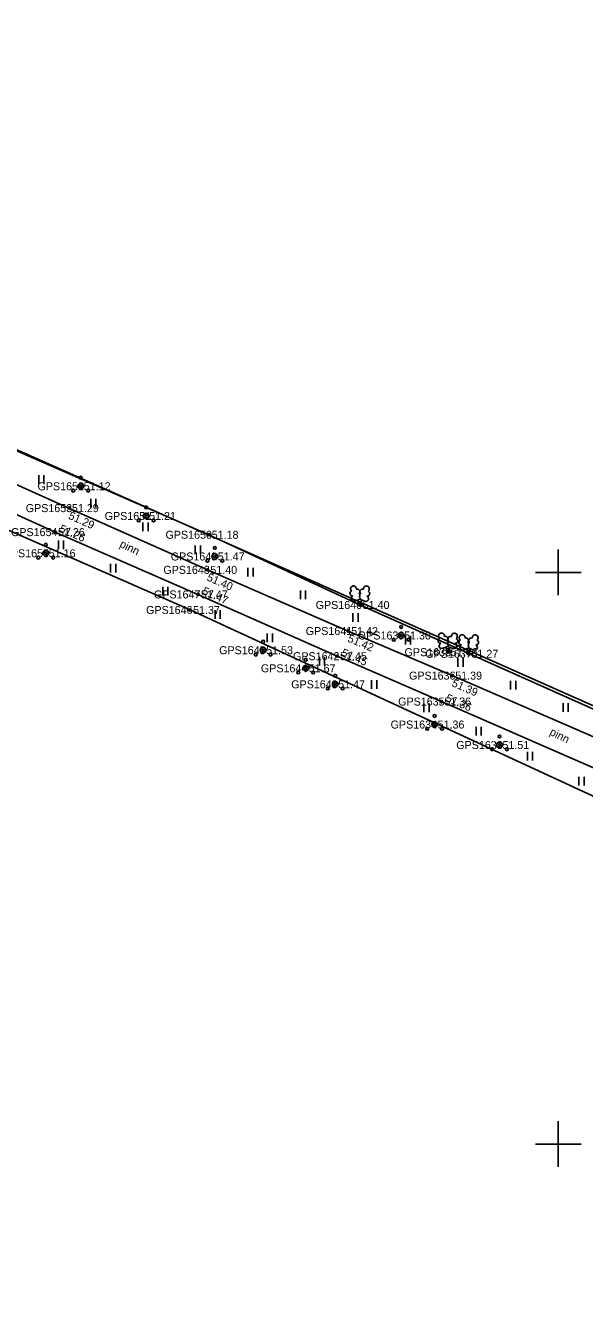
# Model space of a CAD drawing. Extents: x 551623 to 559850, y 6561220 to 6567135.
# Drawn here: x 556303.4 to 556352.3, y 6565186.2 to 6565297.8 of the extents above; entities that cross this region are included whole.
import ezdxf

# ---------------------------------------------------------------- set-up
doc = ezdxf.new("R2010")
doc.units = 0
for name, color, linetype in [('HALJASTUS', 7, 'Continuous'), ('KORGUS-EH2000', 7, 'Continuous'), ('MOOTKORG-EH2000', 7, 'Continuous'), ('MOOTMPUNKT', 7, 'Continuous'), ('MOOTNR', 7, 'Continuous'), ('MOOTPIIR', 7, 'Continuous'), ('PIIR', 7, 'Continuous'), ('PUU', 7, 'Continuous'), ('TEE', 7, 'Continuous'), ('VORK', 7, 'Continuous')]:
    doc.layers.add(name, color=color, linetype=linetype)

msp = doc.modelspace()

# ---------------------------------------------------------------- linework, layer by layer
at = {"layer": 'HALJASTUS'}
for p, q in [((556304.57, 6565258.49), (556304.57, 6565257.73)), ((556305.03, 6565258.49), (556305.03, 6565257.73)), ((556309.12, 6565256.42), (556309.12, 6565255.66)), ((556309.58, 6565256.42), (556309.58, 6565255.66)), ((556313.67, 6565254.35), (556313.67, 6565253.59)), ((556314.13, 6565254.35), (556314.13, 6565253.59)), ((556306.29, 6565252.8), (556306.29, 6565252.04)), ((556306.74, 6565252.8), (556306.74, 6565252.04)), ((556318.26, 6565252.36), (556318.26, 6565251.6)), ((556318.72, 6565252.36), (556318.72, 6565251.6)), ((556310.85, 6565250.76), (556310.85, 6565250)), ((556311.31, 6565250.76), (556311.31, 6565250)), ((556322.85, 6565250.39), (556322.85, 6565249.63)), ((556323.31, 6565250.39), (556323.31, 6565249.63)), ((556315.42, 6565248.73), (556315.42, 6565247.97)), ((556315.87, 6565248.73), (556315.87, 6565247.97)), ((556327.45, 6565248.41), (556327.45, 6565247.65)), ((556327.9, 6565248.41), (556327.9, 6565247.65)), ((556319.99, 6565246.69), (556319.99, 6565245.93)), ((556320.44, 6565246.69), (556320.44, 6565245.93)), ((556332.04, 6565246.44), (556332.04, 6565245.68)), ((556332.5, 6565246.44), (556332.5, 6565245.68)), ((556324.55, 6565244.65), (556324.55, 6565243.89)), ((556325.01, 6565244.65), (556325.01, 6565243.89)), ((556336.64, 6565244.46), (556336.64, 6565243.7)), ((556337.09, 6565244.46), (556337.09, 6565243.7)), ((556329.12, 6565242.62), (556329.12, 6565241.86)), ((556329.57, 6565242.62), (556329.57, 6565241.86)), ((556341.23, 6565242.49), (556341.23, 6565241.73)), ((556341.68, 6565242.49), (556341.68, 6565241.73)), ((556333.68, 6565240.58), (556333.68, 6565239.82)), ((556334.14, 6565240.58), (556334.14, 6565239.82)), ((556345.82, 6565240.52), (556345.82, 6565239.76)), ((556346.28, 6565240.52), (556346.28, 6565239.76)), ((556338.25, 6565238.54), (556338.25, 6565237.78)), ((556338.71, 6565238.54), (556338.71, 6565237.78)), ((556350.42, 6565238.55), (556350.42, 6565237.79)), ((556350.87, 6565238.55), (556350.87, 6565237.79)), ((556342.81, 6565236.48), (556342.81, 6565235.72)), ((556343.26, 6565236.48), (556343.26, 6565235.72)), ((556347.31, 6565234.3), (556347.31, 6565233.54)), ((556347.76, 6565234.3), (556347.76, 6565233.54)), ((556351.81, 6565232.13), (556351.81, 6565231.36)), ((556352.26, 6565232.13), (556352.26, 6565231.36))]:
    msp.add_line(p, q, dxfattribs=at)
at = {"layer": 'KORGUS-EH2000'}
for centre in [(556308.25, 6565257.53), (556307.22, 6565255.62), (556306, 6565253.52), (556319.44, 6565253.29), (556305.19, 6565251.67), (556319.32, 6565250.22), (556318.5, 6565248.07), (556332.64, 6565247.15), (556317.81, 6565246.71), (556331.63, 6565244.87), (556330.66, 6565242.67), (556342.15, 6565242.88), (556330.5, 6565240.21), (556340.73, 6565240.97), (556339.78, 6565238.7), (556339.19, 6565236.69)]:
    msp.add_circle(centre, 0.1, dxfattribs=at)
at = {"layer": 'MOOTMPUNKT'}
for centre in [(556308.25, 6565257.53), (556307.22, 6565255.62), (556313.97, 6565254.93), (556306, 6565253.52), (556319.44, 6565253.29), (556305.19, 6565251.67), (556319.97, 6565251.39), (556319.32, 6565250.22), (556318.5, 6565248.07), (556332.64, 6565247.15), (556317.81, 6565246.71), (556331.63, 6565244.87), (556336.26, 6565244.48), (556324.2, 6565243.19), (556330.66, 6565242.67), (556340.34, 6565243.02), (556342.15, 6565242.88), (556327.92, 6565241.61), (556330.5, 6565240.21), (556340.73, 6565240.97), (556339.78, 6565238.7), (556339.19, 6565236.69), (556344.86, 6565234.9)]:
    msp.add_circle(centre, 0.1, dxfattribs=at)
at = {"layer": 'MOOTPIIR'}
for points in [[(556444.3, 6565198.68), (556419.03, 6565208.86), (556407.25, 6565214.28), (556381.48, 6565225.36), (556332.64, 6565247.15), (556319.44, 6565253.29), (556278.3, 6565271.26)], [(556293.31, 6565257.46), (556317.81, 6565246.71), (556360.31, 6565227.07), (556390.3, 6565214.09), (556436.48, 6565194.19), (556449.65, 6565188.22)]]:
    msp.add_lwpolyline(points, dxfattribs=at)
at = {"layer": 'PIIR'}
for points in [[(556217.39, 6565298.59), (556213.87, 6565303.19), (556229.81, 6565311.25), (556335.44, 6565331.24), (556350.73, 6565342.07), (556507.54, 6565334), (556519.21, 6565368.05), (556548.5, 6565368.1), (556612.15, 6565380.04), (556615.14, 6565380.2), (556613.56, 6565366.23), (556611.32, 6565356.67), (556591.74, 6565273.2), (556570.09, 6565180.67), (556561.87, 6565145.74), (556557.67, 6565147.61), (556393.49, 6565220.36)], [(556206.35, 6565280.04), (556217.39, 6565298.59), (556393.49, 6565220.36), (556274.8, 6564990.28), (556228.34, 6565008.72), (556105.05, 6565057.69), (556140.52, 6565135.89), (556229.38, 6565104.35), (556274.08, 6565194.99), (556184.08, 6565232.1), (556196.52, 6565258.88), (556203.12, 6565272.11)]]:
    msp.add_lwpolyline(points, close=True, dxfattribs=at)
at = {"layer": 'PUU'}
for p, q in [((556332.2, 6565247.48), (556332.65, 6565247.66)), ((556332.64, 6565247.15), (556332.47, 6565247.59)), ((556332.64, 6565247.15), (556332.82, 6565247.59)), ((556333.02, 6565247.15), (556332.64, 6565247.15)), ((556332.65, 6565247.66), (556333.09, 6565247.48)), ((556339.9, 6565243.36), (556340.35, 6565243.53)), ((556340.34, 6565243.02), (556340.17, 6565243.46)), ((556340.34, 6565243.02), (556340.52, 6565243.46)), ((556340.72, 6565243.02), (556340.34, 6565243.02)), ((556340.35, 6565243.53), (556340.79, 6565243.35)), ((556341.71, 6565243.21), (556342.16, 6565243.39)), ((556342.15, 6565242.88), (556341.98, 6565243.32)), ((556342.15, 6565242.88), (556342.33, 6565243.32)), ((556342.53, 6565242.88), (556342.15, 6565242.88)), ((556342.16, 6565243.39), (556342.6, 6565243.21))]:
    msp.add_line(p, q, dxfattribs=at)
for points in [[(556332.65, 6565248.15), (556332.63, 6565248.08), (556332.63, 6565248.06), (556332.64, 6565248.03), (556332.66, 6565247.99), (556332.66, 6565247.97), (556332.65, 6565247.94), (556332.62, 6565247.89), (556332.62, 6565247.86), (556332.62, 6565247.85), (556332.63, 6565247.82), (556332.67, 6565247.76), (556332.67, 6565247.74), (556332.67, 6565247.72), (556332.65, 6565247.68), (556332.65, 6565247.66)], [(556340.35, 6565244.03), (556340.33, 6565243.95), (556340.33, 6565243.93), (556340.34, 6565243.9), (556340.36, 6565243.87), (556340.36, 6565243.85), (556340.35, 6565243.81), (556340.32, 6565243.76), (556340.32, 6565243.74), (556340.32, 6565243.72), (556340.33, 6565243.69), (556340.37, 6565243.63), (556340.37, 6565243.61), (556340.37, 6565243.59), (556340.35, 6565243.56), (556340.35, 6565243.53)], [(556342.16, 6565243.88), (556342.14, 6565243.81), (556342.14, 6565243.79), (556342.15, 6565243.76), (556342.17, 6565243.72), (556342.17, 6565243.7), (556342.16, 6565243.67), (556342.13, 6565243.62), (556342.13, 6565243.59), (556342.13, 6565243.58), (556342.14, 6565243.55), (556342.18, 6565243.49), (556342.18, 6565243.47), (556342.18, 6565243.45), (556342.16, 6565243.41), (556342.16, 6565243.39)]]:
    msp.add_lwpolyline(points, dxfattribs=at)
for centre, radius in [((556308.25, 6565258.28), 0.125), ((556307.6, 6565257.15), 0.125), ((556308.25, 6565257.53), 0.25), ((556308.9, 6565257.15), 0.125), ((556313.97, 6565254.93), 0.25), ((556313.97, 6565255.68), 0.125), ((556313.32, 6565254.55), 0.125), ((556314.62, 6565254.55), 0.125), ((556305.19, 6565251.67), 0.25), ((556305.19, 6565252.42), 0.125), ((556319.97, 6565251.39), 0.25), ((556319.97, 6565252.14), 0.125), ((556304.54, 6565251.29), 0.125), ((556305.84, 6565251.29), 0.125), ((556319.32, 6565251.02), 0.125), ((556320.62, 6565251.02), 0.125), ((556336.26, 6565245.23), 0.125), ((556324.2, 6565243.94), 0.125), ((556335.61, 6565244.11), 0.125), ((556336.26, 6565244.48), 0.25), ((556336.91, 6565244.11), 0.125), ((556323.55, 6565242.81), 0.125), ((556324.2, 6565243.19), 0.25), ((556324.85, 6565242.81), 0.125), ((556327.92, 6565241.61), 0.25), ((556327.92, 6565242.36), 0.125), ((556327.27, 6565241.24), 0.125), ((556328.57, 6565241.24), 0.125), ((556330.5, 6565240.21), 0.25), ((556330.5, 6565240.96), 0.125), ((556329.85, 6565239.84), 0.125), ((556331.15, 6565239.84), 0.125), ((556339.19, 6565237.44), 0.125), ((556338.54, 6565236.32), 0.125), ((556339.19, 6565236.69), 0.25), ((556339.84, 6565236.32), 0.125), ((556344.86, 6565234.9), 0.25), ((556344.86, 6565235.65), 0.125), ((556344.21, 6565234.53), 0.125), ((556345.51, 6565234.53), 0.125)]:
    msp.add_circle(centre, radius, dxfattribs=at)
for centre, radius, start, end in [((556332.01, 6565248.15), 0.224, 111.4304, 274.4987), ((556332.09, 6565248.56), 0.256, 111.5027, 232.5173), ((556332.09, 6565248.56), 0.256, 350.4856, 111.5002), ((556332.42, 6565248.31), 0.224, 308.5041, 111.5725), ((556332.65, 6565247.91), 0.237, 66.7655, 111.5015), ((556332.88, 6565248.31), 0.225, 67.7016, 230.5126), ((556333.22, 6565248.55), 0.256, 67.6168, 188.6314), ((556333.29, 6565248.14), 0.224, 264.6183, 67.6866), ((556333.22, 6565248.55), 0.256, 306.5997, 67.6143), ((556332.12, 6565247.71), 0.237, 111.5014, 291.5004), ((556333.18, 6565247.7), 0.237, 247.6166, 67.6155), ((556339.71, 6565244.02), 0.224, 111.4304, 274.4987), ((556339.79, 6565244.44), 0.256, 111.5027, 232.5173), ((556339.82, 6565243.58), 0.237, 111.5014, 291.5004), ((556339.79, 6565244.44), 0.256, 350.4856, 111.5002), ((556340.12, 6565244.19), 0.224, 308.5041, 111.5725), ((556340.35, 6565243.79), 0.237, 66.7655, 111.5015), ((556340.58, 6565244.18), 0.225, 67.7016, 230.5126), ((556340.92, 6565244.43), 0.256, 67.6168, 188.6314), ((556340.88, 6565243.57), 0.237, 247.6166, 67.6155), ((556340.99, 6565244.01), 0.224, 264.6183, 67.6866), ((556340.92, 6565244.43), 0.256, 306.5997, 67.6143), ((556341.52, 6565243.88), 0.224, 111.4304, 274.4987), ((556341.6, 6565244.29), 0.256, 111.5027, 232.5173), ((556341.63, 6565243.44), 0.237, 111.5014, 291.5004), ((556341.6, 6565244.29), 0.256, 350.4856, 111.5002), ((556341.93, 6565244.04), 0.224, 308.5041, 111.5725), ((556342.16, 6565243.64), 0.237, 66.7655, 111.5015), ((556342.39, 6565244.04), 0.225, 67.7016, 230.5126), ((556342.73, 6565244.28), 0.256, 67.6168, 188.6314), ((556342.8, 6565243.87), 0.224, 264.6183, 67.6866), ((556342.73, 6565244.28), 0.256, 306.5997, 67.6143), ((556342.69, 6565243.43), 0.237, 247.6166, 67.6155)]:
    msp.add_arc(centre, radius, start, end, dxfattribs=at)
at = {"layer": 'TEE'}
for points in [[(556212.52, 6565297.66), (556233.2, 6565288.81), (556257.43, 6565277.89), (556277.38, 6565268.88), (556295.26, 6565260.97), (556307.22, 6565255.62), (556319.32, 6565250.22), (556331.63, 6565244.87), (556340.73, 6565240.97), (556360.59, 6565232.35), (556381.38, 6565222.92), (556405.85, 6565212.41), (556418.1, 6565207.03), (556442.44, 6565196.36)], [(556563.78, 6565138.67), (556560.87, 6565140.85), (556553.17, 6565143.6), (556545.59, 6565147.01), (556535.18, 6565151.57), (556522.84, 6565156.96), (556502.18, 6565166.78), (556486.19, 6565174.09), (556471.01, 6565180.89), (556450.06, 6565190.45), (556440.99, 6565194.27), (556416.95, 6565204.81), (556405, 6565210.26), (556380.26, 6565220.95), (556359.75, 6565229.99), (556339.78, 6565238.7), (556330.66, 6565242.67), (556318.5, 6565248.07), (556306, 6565253.52), (556294.08, 6565258.94), (556276.19, 6565266.76), (556256.29, 6565275.58), (556232.17, 6565286.79), (556209.59, 6565295.96)]]:
    msp.add_lwpolyline(points, dxfattribs=at)
at = {"layer": 'VORK'}
for p, q in [((556350, 6565252), (556350, 6565248)), ((556348, 6565250), (556352, 6565250)), ((556350, 6565202), (556350, 6565198)), ((556348, 6565200), (556352, 6565200))]:
    msp.add_line(p, q, dxfattribs=at)

# ---------------------------------------------------------------- texts
at = {"layer": 'KORGUS-EH2000'}
for s, p in [(' 51.12', (556308.25, 6565257.18)), (' 51.18', (556319.44, 6565252.94)), (' 51.16', (556305.19, 6565251.32)), (' 51.37', (556317.81, 6565246.36)), (' 51.40', (556332.64, 6565246.8)), (' 51.27', (556342.15, 6565242.53)), (' 51.47', (556330.5, 6565239.86)), (' 51.36', (556339.19, 6565236.34))]:
    msp.add_text(s, height=0.7, dxfattribs=at).set_placement(p)
for s, rotation, p in [(' 51.29', 335.9424, (556306.87, 6565254.82)), (' 51.26', 336.4346, (556306.07, 6565253.68)), (' 51.40', 336.495, (556318.97, 6565249.42)), (' 51.47', 336.052, (556318.57, 6565248.23)), (' 51.42', 336.8382, (556331.28, 6565244.07)), (' 51.45', 336.5056, (556330.73, 6565242.83)), (' 51.39', 336.5081, (556340.39, 6565240.17)), (' 51.36', 336.4286, (556339.85, 6565238.86))]:
    msp.add_text(s, height=0.7, rotation=rotation, dxfattribs=at).set_placement(p)
at = {"layer": 'MOOTKORG-EH2000'}
for s, p in [(' 51.12', (556308.25, 6565257.18)), (' 51.29', (556307.22, 6565255.27)), (' 51.21', (556313.97, 6565254.58)), (' 51.26', (556306, 6565253.17)), (' 51.18', (556319.44, 6565252.94)), (' 51.16', (556305.19, 6565251.32)), (' 51.47', (556319.97, 6565251.04)), (' 51.40', (556319.32, 6565249.87)), (' 51.47', (556318.5, 6565247.72)), (' 51.37', (556317.81, 6565246.36)), (' 51.40', (556332.64, 6565246.8)), (' 51.42', (556331.63, 6565244.52)), (' 51.30', (556336.26, 6565244.13)), (' 51.53', (556324.2, 6565242.84)), (' 51.45', (556330.66, 6565242.32)), (' 51.46', (556340.34, 6565242.67)), (' 51.27', (556342.15, 6565242.53)), (' 51.67', (556327.92, 6565241.26)), (' 51.47', (556330.5, 6565239.86)), (' 51.39', (556340.73, 6565240.62)), (' 51.36', (556339.78, 6565238.35)), (' 51.36', (556339.19, 6565236.34)), (' 51.51', (556344.86, 6565234.55))]:
    msp.add_text(s, height=0.7, dxfattribs=at).set_placement(p)
at = {"layer": 'MOOTNR'}
for s, p in [('GPS1652 ', (556304.47, 6565257.18)), ('GPS1653 ', (556303.44, 6565255.27)), ('GPS1651 ', (556310.34, 6565254.58)), ('GPS1654 ', (556302.15, 6565253.17)), ('GPS1650 ', (556315.66, 6565252.94)), ('GPS1655 ', (556301.41, 6565251.32)), ('GPS1649 ', (556316.12, 6565251.04)), ('GPS1648 ', (556315.47, 6565249.87)), ('GPS1647 ', (556314.65, 6565247.72)), ('GPS1646 ', (556313.96, 6565246.36)), ('GPS1640 ', (556328.79, 6565246.8)), ('GPS1641 ', (556327.92, 6565244.52)), ('GPS1639 ', (556332.48, 6565244.13)), ('GPS1645 ', (556320.35, 6565242.84)), ('GPS1642 ', (556326.81, 6565242.32)), ('GPS1638 ', (556336.56, 6565242.67)), ('GPS1637 ', (556338.37, 6565242.53)), ('GPS1644 ', (556324, 6565241.26)), ('GPS1643 ', (556326.65, 6565239.86)), ('GPS1636 ', (556336.95, 6565240.62)), ('GPS1635 ', (556336, 6565238.35)), ('GPS1634 ', (556335.34, 6565236.34)), ('GPS1633 ', (556341.08, 6565234.55))]:
    msp.add_text(s, height=0.7, dxfattribs=at).set_placement(p)
at = {"layer": 'TEE'}
for rotation, p in [(334.4399, (556311.59, 6565252.25)), (333.375, (556349.18, 6565235.82))]:
    msp.add_text('pinn', height=0.7, rotation=rotation, dxfattribs=at).set_placement(p)

doc.saveas('drawing.dxf')
